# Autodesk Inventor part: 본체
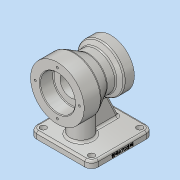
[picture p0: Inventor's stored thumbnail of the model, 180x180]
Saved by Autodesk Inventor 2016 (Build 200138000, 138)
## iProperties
Created: 2019-01
Part Number: 본체
Material: 알루미늄 6061
Document SubType Name: Modeling
Designer: MIRAE
Density: 2.7 g/cm^3
Appearance: 알루미늄 - 평지
Mass: 898.816 g
Surface Area: 600.964 cm^2
Volume: 332.895 cm^3
Author: MIRAE
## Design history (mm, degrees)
sketch "스케치1"
  geometry: L1 (0, 0)-(-80, 0); L2 (0, 0)-(0, 35); L3 (0, 35)-(-15, 35); L4 (-15, 35)-(-20.874, 28); L5 (-20.874, 28)-(-34.215, 28); L6 (-34.215, 28)-(-55, 40); L7 (-55, 40)-(-80, 40); L8 (-80, 40)-(-80, 0)
  constraints: 16 end point, 2 parallel, 2 perpendicular, 1 horizontal, 1 vertical
  dimensions: "d8" = 80 distance of L1.start L1.end; "d9" = 70 diameter of L3 L1; "d10" = 50 deg angle of L5 L4; "d11" = 30 deg angle of L5 L6; "d12" = 25 distance of L6.end L7.end; "d13" = 80 diameter of L7 L1; "d14" = 15 distance of L2.end L3.end; "d15" = 56 diameter of L5 L1
revolve "회전1" sketch "스케치1" stored, may be unused: angle "d16" = 90 deg
sketch "스케치2"
  geometry: L1 (0, 0)-(-80, 0); L2 (0, 0)-(0, 20); L3 (0, -35)-(0, 35) reference; L4 (-15, -35)-(-15, 35) reference; L5 (0, 20)-(-17, 20); L6 (-17, 20)-(-17, 16); L7 (-17, 16)-(-60, 16); L8 (-60, 16)-(-60, 26); L9 (-60, 26)-(-80, 26); L10 (-80, 26)-(-80, 0); L11 (-80, -40)-(-80, 40) reference
  constraints: 16 end point, 5 perpendicular, 1 collinear, 1 horizontal, 1 point on line
  dimensions: "d17" = 80 distance of L1.start L1.end; "d18" = 20 distance of L1.start L2.end; "d20" = 17 distance of L2.end L5.end; "d21" = 20 distance of L8.end L9.end; "d22" = 32 diameter of L7 L1; "d23" = 52 diameter of L9 L1
revolve "회전2" sketch "스케치2" stored, may be unused: angle "d24" = 90 deg
sketch "스케치3"
  geometry: L1 (0, 0)-(0, 33); C1 r 40 at (0, 0) reference; 2 further points
  constraints: 2 end point, 1 coincident, 1 vertical
  dimensions: "d25" = 33 distance of L1.start L1.end
hole "구멍1" sketch "스케치3" at (0, 33) diameter "d26" = 3.242; stored, may be unused: countersink angle "d30" = 90 deg, drill point angle "d32" = 118 deg; dims "d27" = 9, "d28" = 4, "d29" = 2, "d31" = 11
sketch "스케치4"
  geometry: L1 (0, 0)-(0, -27.5); 1 further point
  constraints: 2 end point, 1 coincident, 1 vertical
  dimensions: "d36" = 27.5 distance of L1.start L1.end
hole "구멍2" sketch "스케치4" at (0, -27.5) diameter "d37" = 3.242; stored, may be unused: countersink angle "d41" = 90 deg, drill point angle "d43" = 118 deg; dims "d38" = 9, "d39" = 4, "d40" = 2, "d42" = 11
node "작업 평면1"
sketch "스케치5"
  geometry: L1 (-46, 17)-(46, 17); L2 (46, 17)-(46, -75); L3 (46, -75)-(-46, -75); L4 (-46, -75)-(-46, 17); L5 (-46, 17)-(46, -75); L6 (46, 17)-(-46, -75); L7 (40, -80)-(-40, -80) reference; 3 further points
  constraints: 12 end point, 3 midpoint, 2 parallel, 1 horizontal, 1 perpendicular, 1 vertical alignment
  dimensions: "d48" = 92 distance of L2.end L3.end; "d49" = 92 distance of L1.end L2.end; "d50" = 5 distance between parallel lines of L7 L3
extrude "돌출1" join sketch "스케치5" distance "d51" = 10; taper "d52" = 0 deg
fillet "모깎기1" dims "d53" = 10
fillet "모깎기2" dims "d54" = 3
sketch "스케치6"
  geometry: L1 (-36, -75)-(36, -75) reference; C1 r 16 at (0, -45); 1 further point
  constraints: 1 centre point, 1 vertical alignment
  dimensions: "d55" = 32 diameter of C1; "d56" = 30 distance from line of L1 C1.centre
extrude "돌출2" join sketch "스케치6" stored distance "d57" = 10; taper "d58" = 0 deg
sketch "스케치7"
  geometry: L1 (-65, -70)-(7, -70) reference; L2 (17, -80)-(17, -73) reference; L3 (-1.159, -52.504)-(7, -70); L4 (7, -70)-(-65, -70) reference; 1 further point
  constraints: 2 end point, 1 point on line
  dimensions: "d60" = 10 distance from line of L2 L3.end; "d61" = 25 deg angle of L2 L3
feature "리브1" sketch "스케치7" dims "d62" = 1, "d63" = 10, "d64" = 0, "d65" = 0, "d66" = 1, "d67" = 1
sketch "스케치8"
  geometry: 1 further point
hole "구멍3" diameter "d71" = 9; stored, may be unused: countersink angle "d75" = 90 deg, drill point angle "d77" = 118 deg; dims "d69" = 10, "d70" = 10, "d72" = 8, "d73" = 4, "d74" = 2, "d76" = 11.8
sketch "스케치9"
  geometry: L1 (-7, -10)-(0, -10) reference; L2 (-7, 0)-(-7, 72) reference; L3 (0, 0)-(-7, 0) reference; L4 (0, 72)-(0, 0) reference; L5 (-7, 72)-(0, 72) reference; 2 further points
  constraints: 1 other
  dimensions: "d84" = 46 distance from line of L1 point (-4, 36); "d85" = 4 distance from line of L4 point (-4, 36)
feature "엠보싱1" sketch "스케치9" dims "d17" = 80, "d18" = 20, "d20" = 17, "d21" = 20, "d22" = 32, "d23" = 52, "d86" = 0.5, "d87" = 0
fillet "모깎기3" dims "d88" = 1
fillet "모깎기4" dims "d89" = 0.6
chamfer "모따기1" distance "d90" = 1; stored, may be unused: second distance "d91" = 2, angle "d92" = 45 deg
chamfer "모따기2" distance "d93" = 1; stored, may be unused: second distance "d94" = 2, angle "d95" = 45 deg
fillet "모깎기5" dims "d96" = 3
fillet "모깎기6" dims "d97" = 3
fillet "모깎기8" dims "d99" = 3
fillet "모깎기9" dims "d100" = 3
feature "분할1"
node "솔리드1"
pattern_circular "원형 패턴1" dims angle "d34" = 360 deg
pattern_circular "원형 패턴2" dims angle "d45" = 360 deg
pattern_linear "직사각형 패턴1" dims "d80" = 72, "d83" = 72
node "투영된 루프1"
